
// ===== library: MasterCopy "SIKO_AG2X_Tags_1" =====

VAR_GLOBAL   // PLC tag table "SIKO_AG2X_Tags_1"
   "Drive1ControlWord" AT %QW256 : Word;
   "Drive1TargetValue" AT %QD258 : DWord;
   "Drive1DigOutControl" AT %QB262 : Byte;
   "Drive1StatusWord" AT %IW256 : Word;
   "Drive1ActualValue" AT %ID258 : DWord;
   "Drive1DigInStatus" AT %IB262 : Byte;
END_VAR

// ===== library: MasterCopy "SIKO_AG2X" =====

FUNCTION_BLOCK "SIKO_AG2X"   // FB1, SCL
TITLE = Function block for SIKO-AG2X
{ S7_Optimized_Access := 'FALSE' }
AUTHOR : Hof
VERSION : 1.1
// Minor Changes
BEGIN
END_FUNCTION_BLOCK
